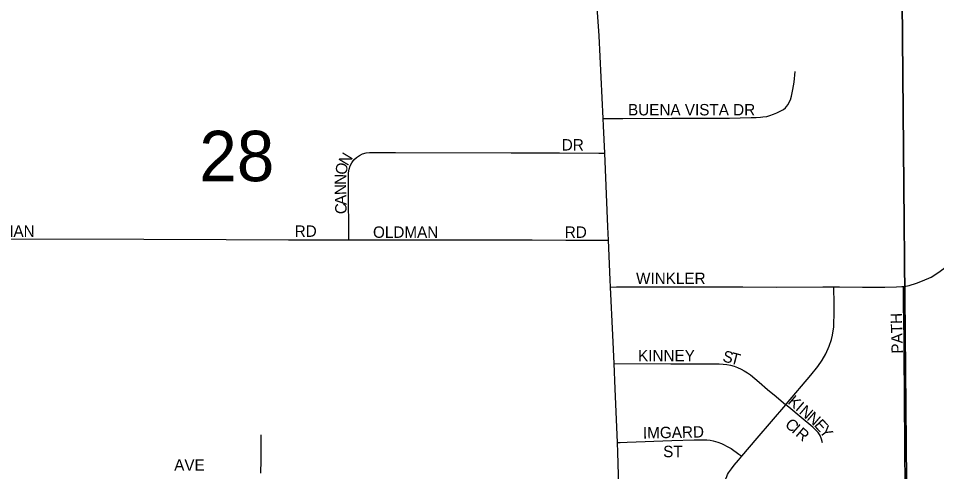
# Model space of a CAD drawing. Extents: x 1985906 to 2360102, y 891258 to 1222054.
# Drawn here: x 2121160 to 2125185, y 1032490 to 1034477 of the extents above; entities that cross this region are included whole.
import ezdxf

# ---------------------------------------------------------------- set-up
doc = ezdxf.new("R2010")
doc.units = 0
for name, color, linetype in [('GM_X_City_Street', 7, 'Continuous'), ('GM_X_City_Street_Text', 7, 'Continuous'), ('GM_X_Section', 7, 'Continuous'), ('GM_X_Section_Text', 7, 'Continuous')]:
    doc.layers.add(name, color=color, linetype=linetype)

msp = doc.modelspace()

# ---------------------------------------------------------------- linework, layer by layer
at = {"layer": 'GM_X_City_Street'}
for points in [[(2123723, 1034038.3), (2123705.5, 1034399.6), (2123691.3, 1034609.2), (2123688.5, 1034658.1)], [(2123723, 1034038.3), (2123744.1, 1034038), (2123768.7, 1034037.7), (2123810, 1034037.6), (2124024.6, 1034039.3), (2124123.6, 1034039), (2124222.5, 1034039.2), (2124276.6, 1034040), (2124324, 1034040.8), (2124372.4, 1034042), (2124393.6, 1034042.4), (2124412.8, 1034043.7), (2124423.2, 1034044.5), (2124441.1, 1034047), (2124454, 1034051.1), (2124469, 1034056.2), (2124484.4, 1034062.4), (2124495.5, 1034068.4), (2124512.8, 1034077.8), (2124521.5, 1034084.9), (2124526.9, 1034090.7), (2124533.2, 1034098.7), (2124539, 1034109.4), (2124543.6, 1034119.9), (2124548.6, 1034136.5), (2124551.5, 1034150.7), (2124554.4, 1034164.5), (2124560.4, 1034197.2), (2124565.3, 1034244.5)], [(2123729.9, 1033886.4), (2123724.6, 1034006), (2123723, 1034038.3)], [(2122609.2, 1033506), (2122608.3, 1033571.6), (2122607.4, 1033670.5), (2122606.5, 1033767.9), (2122607, 1033800), (2122609.7, 1033815.3), (2122614.7, 1033830.1), (2122621.9, 1033844), (2122631, 1033856.6), (2122642, 1033867.4), (2122654.8, 1033876.1), (2122668.9, 1033882.6), (2122683.9, 1033886.8), (2122699.3, 1033888.5), (2122813.7, 1033888.5), (2123320.7, 1033887.7), (2123474.8, 1033887.2), (2123532, 1033887), (2123704, 1033886.4), (2123729.9, 1033886.4)], [(2123746.6, 1033505.1), (2123744.1, 1033563.1), (2123729.9, 1033886.4)], [(2120857.2, 1033510.4), (2120886.8, 1033510.5), (2121709.7, 1033508.3), (2122071.7, 1033507.3), (2122344.3, 1033506.5), (2122422.1, 1033506.4), (2122515.7, 1033506.2), (2122609.2, 1033506)], [(2122609.2, 1033506), (2122722.4, 1033506.4), (2123034.4, 1033505.6), (2123412.1, 1033505.8), (2123559.8, 1033504.7), (2123691.4, 1033505), (2123746.6, 1033505.1)], [(2123755.6, 1033299), (2123754.1, 1033330.6), (2123746.6, 1033505.1)], [(2125039.3, 1033302), (2125050.2, 1033303.5), (2125064.4, 1033306.4), (2125096.2, 1033315.3), (2125122.8, 1033325.5), (2125160, 1033342.3), (2125189.7, 1033360.7), (2125216.2, 1033380.6), (2125239.2, 1033402.1), (2125283.2, 1033446), (2125303.8, 1033466.3)], [(2123755.6, 1033299), (2123782.3, 1033299.2), (2123860.9, 1033299.9), (2123991.9, 1033300), (2124335.6, 1033299.8), (2124482.9, 1033299), (2124686.5, 1033299.5), (2124734.6, 1033299.5)], [(2123771.9, 1032963.4), (2123765.9, 1033087.4), (2123755.6, 1033299)], [(2124523.2, 1032783.1), (2124526.5, 1032787), (2124633.3, 1032912.1), (2124664, 1032950.6), (2124682.5, 1032977.8), (2124698.8, 1033006.3), (2124713.8, 1033039.3), (2124723.1, 1033068.5), (2124728.2, 1033087.6), (2124731.6, 1033106.3), (2124733.8, 1033122.8), (2124734.6, 1033139.8), (2124735.5, 1033180.5), (2124735.1, 1033236.5), (2124734.7, 1033286.9), (2124734.6, 1033299.5)], [(2124734.6, 1033299.5), (2124758.5, 1033299.5), (2124860.2, 1033299), (2124958.2, 1033298.9), (2125009.3, 1033299.4), (2125031.3, 1033301), (2125039.3, 1033302)], [(2125048.4, 1032254.6), (2125047.6, 1032347.9), (2125047.7, 1032397), (2125046.7, 1032471.8), (2125045.8, 1032544), (2125044.6, 1032672.4), (2125044.3, 1032738.6), (2125044.4, 1032786.6), (2125043.7, 1032829.1), (2125043.7, 1032884.5), (2125042.9, 1032938.3), (2125042.4, 1032998.5), (2125041.6, 1033060.1), (2125040.3, 1033159.6), (2125039.8, 1033208.8), (2125039.9, 1033243.7), (2125039.5, 1033288.1), (2125039.3, 1033302)], [(2123771.9, 1032963.4), (2124019.4, 1032962.6), (2124163, 1032962.5), (2124232.1, 1032961.9), (2124248.6, 1032961), (2124264.9, 1032959), (2124281, 1032955.8), (2124296.9, 1032951.5), (2124312.4, 1032946), (2124327.4, 1032939.4), (2124341.8, 1032931.6), (2124355.8, 1032923), (2124369.2, 1032913.6), (2124406.8, 1032881.8), (2124444, 1032849.4), (2124481.2, 1032818.8), (2124523.2, 1032783.1)], [(2123785.4, 1032617.1), (2123776.4, 1032852.9), (2123771.9, 1032963.4)], [(2124330.9, 1032557.6), (2124398.7, 1032637), (2124523.2, 1032783.1)], [(2124684.1, 1032616.2), (2124680.5, 1032632.4), (2124674.3, 1032647.6), (2124665.1, 1032661.2), (2124654, 1032673.3), (2124641.9, 1032684.5), (2124590.5, 1032726.9), (2124536.5, 1032772), (2124523.2, 1032783.1)], [(2122223.4, 1032482.7), (2122223.8, 1032539.7), (2122224, 1032565.7), (2122224.2, 1032594.4), (2122224.7, 1032651.3)], [(2123785.4, 1032617.1), (2123797.2, 1032617.6), (2123828, 1032618.8), (2124023.7, 1032626.2), (2124122.1, 1032629.7), (2124154.7, 1032628.9), (2124177.8, 1032628.6), (2124191.6, 1032627.3), (2124204.6, 1032625.3), (2124225.5, 1032619.4), (2124241.2, 1032612.9), (2124252.9, 1032607.7), (2124264.3, 1032601.8), (2124283.4, 1032590.9), (2124318.2, 1032566.5), (2124330.9, 1032557.6)], [(2123832.3, 1031208), (2123819.7, 1031558.3), (2123810.7, 1031820.4), (2123801.8, 1032099), (2123796.3, 1032279.3), (2123787.1, 1032574.3), (2123785.4, 1032617.1)], [(2124251.9, 1032248.1), (2124249.4, 1032330.8), (2124248, 1032391.3), (2124249.2, 1032407.7), (2124251.7, 1032424), (2124254.9, 1032439.8), (2124259.6, 1032455.1), (2124264.6, 1032468.6), (2124268.5, 1032477.1), (2124273.1, 1032484.4), (2124285.4, 1032502.6), (2124296.9, 1032517.4), (2124316, 1032540.3), (2124330.9, 1032557.6)]]:
    msp.add_lwpolyline(points, dxfattribs=at)
at = {"layer": 'GM_X_Section'}
for points in [[(2119771.9, 1036177.8), (2125019.2, 1036172.5), (2125066.6, 1030831.6), (2119807.2, 1030846.8)], [(2125019.2, 1036172.5), (2130202.8, 1036134.8), (2130280.1, 1030804), (2125066.6, 1030831.6)]]:
    msp.add_lwpolyline(points, close=True, dxfattribs=at)

# ---------------------------------------------------------------- texts
at = {"layer": 'GM_X_City_Street_Text'}
for s, rotation, p in [('BUENA VISTA DR', 0, (2123832.1, 1034051.5)), ('DR', 0, (2123541.7, 1033897.5)), ('N', 58.845, (2122603.3, 1033827)), ('O', 79.5388, (2122597, 1033788.2)), ('N', 88.6668, (2122596.2, 1033746.3)), ('N', 91.4862, (2122597.3, 1033702.9)), ('A', 91.503, (2122598.5, 1033659)), ('C', 91.4819, (2122599.5, 1033619.4)), ('OLDMAN', 0, (2120945.7, 1033519.1)), ('RD', 0, (2122371.3, 1033519.1)), ('OLDMAN', 0, (2122714.5, 1033514.7)), ('RD', 0, (2123554.9, 1033514.7)), ('WINKLER', 0, (2123867.3, 1033312.3)), ('PATH', 91.541, (2125037.1, 1033007.8)), ('KINNEY', 0, (2123876.1, 1032973.5)), ('S', 346.7391, (2124243.4, 1032973.3)), ('T', 345.3872, (2124277.3, 1032965.3)), ('K', 319.3466, (2124529, 1032790.9)), ('I', 319.3323, (2124562.4, 1032762.2)), ('N', 319.3417, (2124579, 1032747.9)), ('N', 319.3466, (2124612.4, 1032719.2)), ('IMGARD', 1.0207, (2123897.9, 1032634.7)), ('C', 318.5742, (2124516.2, 1032691.1)), ('I', 318.7567, (2124546, 1032664.8)), ('R', 319.691, (2124563.3, 1032649.7)), ('E', 312.7202, (2124644.7, 1032691.6)), ('Y', 306.8743, (2124667.7, 1032666.8)), ('ST', 0, (2123986.1, 1032553.1)), ('AVE', 0, (2121843.3, 1032493.9))]:
    msp.add_text(s, height=50, rotation=rotation, dxfattribs=at).set_placement(p)
at = {"layer": 'GM_X_Section_Text'}
msp.add_text('28', height=221, rotation=0, dxfattribs=at).set_placement((2121953.3, 1033763))

doc.saveas('drawing.dxf')
